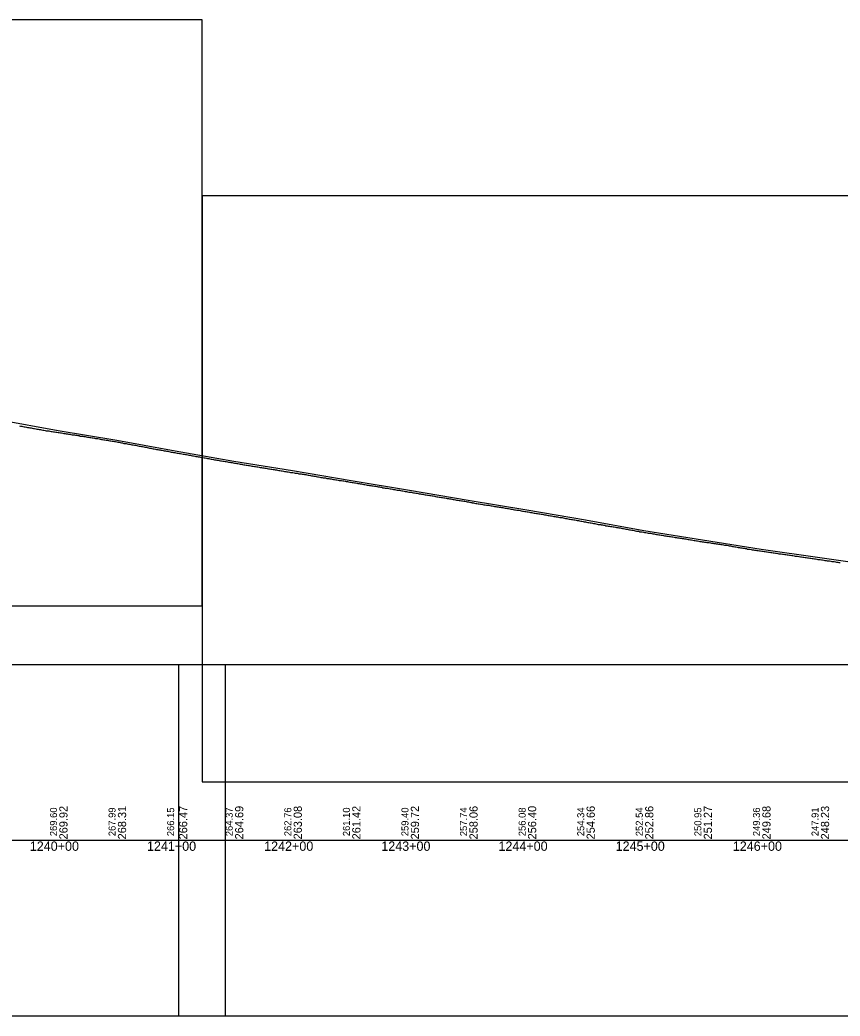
# Model space of a CAD drawing. Extents: x 2898 to 49495, y -15038 to -13538.
# Drawn here: x 13321 to 14021, y -15038 to -14188 of the extents above; entities that cross this region are included whole.
import ezdxf

# ---------------------------------------------------------------- set-up
doc = ezdxf.new("R2010")
doc.units = 0
for name, color, linetype in [('RD_DDB_Profile_EX', 7, 'Continuous'), ('RD_DDB_Profile_PR', 7, 'Continuous'), ('RD_DDB_StaTX', 7, 'Continuous'), ('RD_DDB_StripGrade', 7, 'Continuous'), ('RD_GPK_Profile_Cell', 7, 'Continuous'), ('RD_SHT_ShtClip', 7, 'Continuous')]:
    doc.layers.add(name, color=color, linetype=linetype)

msp = doc.modelspace()

# ---------------------------------------------------------------- linework, layer by layer
at = {"layer": 'RD_DDB_Profile_EX'}
for points in [[(13320.31, -14534.82), (13321.31, -14535), (13322.29, -14535.18), (13323.29, -14535.52), (13324.29, -14535.58), (13325.29, -14535.77), (13326.29, -14535.88), (13327.29, -14536.17), (13328.29, -14536.27), (13329.29, -14536.51), (13330.29, -14536.63), (13331.29, -14536.87), (13332.29, -14536.98), (13333.29, -14537.18), (13334.28, -14537.38), (13335.28, -14537.53), (13336.28, -14537.73), (13337.28, -14537.97), (13338.28, -14538.08), (13339.28, -14538.18), (13340.28, -14538.52), (13341.28, -14538.62), (13342.28, -14538.72), (13343.28, -14539.01), (13344.28, -14539.02), (13345.28, -14539.18), (13346.28, -14539.43), (13347.28, -14539.56), (13348.28, -14539.66)], [(13348.28, -14539.66), (13349.3, -14539.88), (13350.3, -14540.01), (13351.3, -14540.17), (13352.3, -14540.31), (13353.3, -14540.46), (13354.3, -14540.57), (13355.3, -14540.71), (13356.3, -14540.91), (13357.3, -14541.07), (13358.29, -14541.3), (13359.3, -14541.32), (13360.3, -14541.51), (13361.3, -14541.7), (13362.3, -14541.86), (13363.3, -14542.01), (13364.3, -14542.11), (13365.3, -14542.41), (13366.29, -14542.46), (13367.29, -14542.56), (13368.29, -14542.81), (13369.29, -14542.91), (13370.29, -14543.01), (13371.29, -14543.16), (13372.29, -14543.59), (13373.29, -14543.56), (13374.3, -14543.75), (13375.29, -14543.9), (13376.29, -14544.01), (13377.28, -14544.15), (13378.29, -14544.35), (13379.29, -14544.54), (13380.29, -14544.7), (13381.29, -14544.89), (13382.29, -14545.05), (13383.29, -14545.2), (13384.29, -14545.45), (13385.29, -14545.55), (13386.28, -14545.65), (13387.28, -14545.75), (13388.28, -14546), (13389.28, -14546.15), (13390.29, -14546.36), (13391.28, -14546.51), (13392.28, -14546.66), (13393.29, -14546.85), (13394.28, -14547), (13395.42, -14547.19), (13396.41, -14547.34), (13397.42, -14547.5), (13398.41, -14547.61), (13399.42, -14547.81), (13400.41, -14548.01), (13401.41, -14548.21), (13402.41, -14548.31), (13403.4, -14548.52), (13404.4, -14548.71), (13405.4, -14548.87), (13406.4, -14549.07), (13407.4, -14549.26), (13408.39, -14549.41), (13409.39, -14549.79), (13410.39, -14549.86), (13411.39, -14549.92), (13412.39, -14550.21), (13413.39, -14550.37), (13414.39, -14550.52), (13415.39, -14550.78), (13416.39, -14550.92), (13417.38, -14551.07), (13418.39, -14551.27), (13419.38, -14551.43), (13420.39, -14551.62), (13421.38, -14551.82), (13422.39, -14552.08), (13423.38, -14552.23), (13424.38, -14552.38), (13425.38, -14552.53), (13426.38, -14552.73), (13427.38, -14552.98), (13428.38, -14553.14), (13429.38, -14553.38), (13430.38, -14553.53), (13431.38, -14553.82), (13432.38, -14553.97), (13433.38, -14554.09), (13434.37, -14554.33), (13435.38, -14554.57), (13436.37, -14554.73), (13437.38, -14554.97), (13438.37, -14555.07), (13439.38, -14555.23), (13440.37, -14555.39), (13440.94, -14555.49), (13441.95, -14555.69), (13442.94, -14555.85), (13443.95, -14556.05), (13444.95, -14556.25), (13445.94, -14556.4), (13446.94, -14556.56), (13447.94, -14556.85)], [(13447.94, -14556.85), (13448.94, -14556.96), (13449.94, -14557.21), (13450.94, -14557.36), (13451.94, -14557.47), (13452.93, -14557.62), (13453.94, -14557.87), (13454.94, -14558.01), (13455.94, -14558.22), (13456.93, -14558.41), (13457.93, -14558.53), (13458.93, -14558.68), (13459.94, -14558.96), (13460.93, -14559.13), (13461.93, -14559.23), (13462.93, -14559.38), (13463.93, -14559.58), (13464.93, -14559.83), (13465.93, -14559.98), (13466.93, -14560.08), (13467.93, -14560.29), (13468.92, -14560.48), (13469.93, -14560.68), (13470.92, -14560.93), (13471.93, -14561.08), (13472.93, -14561.23), (13473.92, -14561.38), (13474.92, -14561.53), (13475.92, -14561.78), (13476.92, -14561.93), (13477.92, -14562.08), (13478.92, -14562.23), (13479.92, -14562.39), (13480.91, -14562.59), (13481.92, -14562.74), (13482.92, -14562.89), (13483.92, -14563.15), (13484.92, -14563.34), (13485.92, -14563.53), (13486.84, -14563.73), (13487.85, -14563.84), (13488.84, -14563.99), (13489.84, -14564.1), (13490.84, -14564.34), (13491.84, -14564.55), (13492.84, -14564.7), (13493.84, -14564.85), (13494.84, -14565), (13495.84, -14565.19), (13496.84, -14565.3), (13497.83, -14565.6), (13498.84, -14565.8), (13499.83, -14565.9), (13500.83, -14566.01), (13501.83, -14566.15), (13502.82, -14566.4), (13503.83, -14566.75), (13504.83, -14566.8), (13505.82, -14566.9), (13506.83, -14567.01), (13507.82, -14567.21), (13508.82, -14567.45), (13509.82, -14567.56), (13510.82, -14567.76), (13511.82, -14568), (13512.82, -14568.11), (13513.81, -14568.31), (13514.82, -14568.41), (13515.82, -14568.65), (13516.81, -14568.8), (13517.81, -14568.91), (13518.81, -14569.21), (13519.81, -14569.26), (13520.81, -14569.41), (13521.8, -14569.51), (13522.81, -14569.76), (13523.8, -14569.92), (13524.8, -14570.16), (13525.81, -14570.27), (13526.8, -14570.47), (13527.8, -14570.62), (13528.8, -14570.77), (13529.8, -14570.97), (13530.8, -14571.07), (13531.8, -14571.17), (13532.79, -14571.42), (13533.8, -14571.52), (13534.79, -14571.67), (13535.79, -14571.82), (13536.79, -14572.02), (13537.69, -14572.13), (13538.69, -14572.28), (13539.69, -14572.48), (13540.69, -14572.58), (13541.69, -14572.82), (13542.69, -14572.93), (13543.69, -14573.08), (13544.69, -14573.33), (13545.68, -14573.43), (13546.68, -14573.68), (13547.69, -14573.73)], [(13547.69, -14573.73), (13548.68, -14573.98), (13549.69, -14573.98), (13550.68, -14574.33), (13551.68, -14574.53), (13552.67, -14574.63), (13553.68, -14574.68), (13554.68, -14574.98), (13555.68, -14575.08), (13556.68, -14575.23), (13557.67, -14575.33), (13558.68, -14575.67), (13559.67, -14575.73), (13560.67, -14575.83), (13561.68, -14576.03), (13562.67, -14576.18), (13563.67, -14576.33), (13564.66, -14576.48), (13565.66, -14576.68), (13566.66, -14576.83), (13567.66, -14576.93), (13568.66, -14577.23), (13569.65, -14577.38), (13570.66, -14577.48), (13571.65, -14577.67), (13572.66, -14577.83), (13573.65, -14577.98), (13574.65, -14578.42), (13575.66, -14578.38), (13576.65, -14578.57), (13577.66, -14578.77), (13578.65, -14578.82), (13579.65, -14579.08), (13580.65, -14579.13), (13581.65, -14579.27), (13582.65, -14579.62), (13583.26, -14579.63), (13584.26, -14579.78), (13585.26, -14580.12), (13586.26, -14580.17), (13587.26, -14580.32), (13588.25, -14580.58), (13589.25, -14580.63), (13590.26, -14580.87), (13591.26, -14580.93), (13592.25, -14581.08), (13593.25, -14581.33), (13594.25, -14581.53), (13595.25, -14581.58), (13596.25, -14581.68), (13597.25, -14581.78), (13598.25, -14582.08), (13599.25, -14582.28), (13600.25, -14582.38), (13601.25, -14582.58), (13602.24, -14582.78), (13603.25, -14582.93), (13604.24, -14583.08), (13605.25, -14583.23), (13606.24, -14583.38), (13607.24, -14583.58), (13608.24, -14583.83), (13609.24, -14583.98), (13610.24, -14584.13), (13611.23, -14584.28), (13612.24, -14584.43), (13613.24, -14584.53), (13614.24, -14584.83), (13615.24, -14584.93), (13616.23, -14585.08), (13617.23, -14585.33), (13618.23, -14585.43), (13619.24, -14585.63), (13620.24, -14585.68), (13621.23, -14585.88), (13622.23, -14586.08), (13623.23, -14586.28), (13624.23, -14586.39), (13625.22, -14586.53), (13625.6, -14586.58), (13626.6, -14586.84), (13627.6, -14586.93), (13628.6, -14587.18), (13629.6, -14587.23), (13630.6, -14587.63), (13631.6, -14587.63), (13632.6, -14587.88), (13633.59, -14587.93), (13634.59, -14588.13), (13635.59, -14588.23), (13636.6, -14588.48), (13637.59, -14588.68), (13638.59, -14588.83), (13639.6, -14589.08), (13640.6, -14589.18), (13641.59, -14589.43), (13642.6, -14589.58), (13643.59, -14589.74), (13644.59, -14589.84), (13645.59, -14590.04), (13646.59, -14590.24)], [(13646.59, -14590.24), (13647.59, -14590.34), (13648.59, -14590.68), (13649.59, -14590.74), (13650.59, -14590.94), (13651.59, -14591.04), (13652.58, -14591.28), (13653.58, -14591.48), (13654.58, -14591.54), (13655.59, -14591.74), (13656.58, -14591.89), (13657.58, -14591.99), (13658.59, -14592.19), (13659.59, -14592.34), (13660.58, -14592.59), (13661.59, -14592.74), (13662.58, -14592.84), (13663.58, -14593.04), (13664.58, -14593.19), (13665.58, -14593.39), (13666.58, -14593.59), (13667.58, -14593.64), (13668.58, -14593.84), (13669.58, -14593.99), (13670.51, -14594.19), (13671.5, -14594.34), (13672.5, -14594.54), (13673.5, -14594.69), (13674.49, -14594.89), (13675.5, -14595.04), (13676.5, -14595.29), (13677.49, -14595.34), (13678.5, -14595.59), (13679.5, -14595.69), (13680.49, -14595.84), (13681.49, -14596.03), (13682.5, -14596.14), (13683.49, -14596.29), (13684.49, -14596.49), (13685.5, -14596.69), (13686.49, -14596.88), (13687.49, -14596.99), (13688.49, -14597.14), (13689.5, -14597.39), (13690.49, -14597.54), (13691.49, -14597.64), (13692.5, -14597.93), (13693.49, -14598.13), (13694.49, -14598.29), (13695.49, -14598.54), (13696.48, -14598.64), (13697.49, -14598.74), (13698.49, -14598.89), (13699.49, -14599.13), (13700.49, -14599.24), (13701.49, -14599.44), (13702.49, -14599.68), (13703.49, -14599.79), (13704.49, -14599.99), (13705.48, -14600.14), (13706.48, -14600.29), (13706.83, -14600.48), (13707.84, -14600.58), (13708.83, -14600.79), (13709.83, -14600.99), (13710.83, -14601.08), (13711.83, -14601.24), (13712.83, -14601.38), (13713.83, -14601.58), (13714.82, -14601.69), (13715.82, -14601.93), (13716.82, -14602.13), (13717.82, -14602.23), (13718.82, -14602.43), (13719.82, -14602.53), (13720.82, -14602.63), (13721.82, -14602.83), (13722.82, -14602.98), (13723.81, -14603.13), (13724.82, -14603.43), (13725.81, -14603.58), (13726.81, -14603.73), (13727.81, -14603.88), (13728.81, -14604.03), (13729.81, -14604.08), (13730.81, -14604.28), (13731.81, -14604.48), (13732.8, -14604.58), (13733.8, -14604.88), (13734.8, -14604.98), (13735.81, -14605.13), (13736.8, -14605.28), (13737.81, -14605.43), (13738.8, -14605.68), (13739.8, -14605.88), (13740.8, -14605.98), (13741.8, -14606.13), (13742.79, -14606.37), (13743.8, -14606.48), (13744.79, -14606.67), (13745.78, -14606.82)], [(13745.78, -14606.82), (13746.55, -14606.87), (13747.56, -14607.02), (13748.55, -14607.22), (13749.56, -14607.52), (13750.55, -14607.67), (13751.55, -14607.92), (13752.56, -14607.97), (13753.56, -14608.07), (13754.55, -14608.27), (13755.55, -14608.42), (13756.55, -14608.67), (13757.55, -14608.82), (13758.55, -14608.97), (13759.55, -14609.27), (13760.55, -14609.37), (13761.55, -14609.52), (13762.54, -14609.67), (13763.55, -14609.87), (13764.55, -14610.02), (13765.54, -14610.22), (13766.55, -14610.32), (13767.55, -14610.47), (13768.55, -14610.72), (13769.54, -14610.82), (13770.54, -14610.97), (13771.54, -14611.22), (13772.55, -14611.37), (13773.54, -14611.52), (13774.54, -14611.67), (13775.54, -14611.87), (13776.53, -14612.07), (13777.54, -14612.12), (13778.54, -14612.37), (13779.54, -14612.52), (13780.54, -14612.72), (13781.54, -14612.92), (13782.54, -14613.07), (13783.54, -14613.17), (13784.41, -14613.42), (13785.42, -14613.52), (13786.41, -14613.77), (13787.41, -14613.92), (13788.41, -14614.22), (13789.41, -14614.32), (13790.41, -14614.52), (13791.41, -14614.62), (13792.4, -14614.82), (13793.41, -14614.92), (13794.41, -14615.17), (13795.4, -14615.32), (13796.41, -14615.62), (13797.41, -14615.72), (13798.4, -14615.92), (13799.41, -14616.07), (13800.41, -14616.27), (13801.41, -14616.42), (13802.4, -14616.62), (13803.41, -14616.77), (13804.41, -14617.07), (13805.4, -14617.17), (13806.4, -14617.37), (13807.4, -14617.62), (13808.4, -14617.72), (13809.4, -14617.87), (13810.4, -14618.12), (13811.4, -14618.27), (13812.4, -14618.57), (13813.4, -14618.67), (13814.39, -14618.87), (13815.4, -14618.97), (13816.4, -14619.12), (13816.95, -14619.22), (13817.94, -14619.42), (13818.94, -14619.57), (13819.94, -14619.72), (13820.94, -14620.02), (13821.94, -14620.12), (13822.93, -14620.37), (13823.93, -14620.47), (13824.93, -14620.62), (13825.93, -14620.82), (13826.93, -14621.07), (13827.93, -14621.12), (13828.93, -14621.27), (13829.93, -14621.47), (13830.93, -14621.62), (13831.93, -14621.82), (13832.93, -14621.92), (13833.93, -14622.22), (13834.93, -14622.37), (13835.93, -14622.47), (13836.93, -14622.82), (13837.93, -14622.92), (13838.93, -14623.02), (13839.93, -14623.27), (13840.93, -14623.52), (13841.93, -14623.57), (13842.93, -14623.82), (13843.93, -14623.92), (13844.93, -14624.23)], [(13844.93, -14624.23), (13845.93, -14624.28), (13846.94, -14624.67), (13847.94, -14624.77), (13848.94, -14624.83), (13849.93, -14625.13), (13850.93, -14625.18), (13851.94, -14625.33), (13852.94, -14625.68), (13853.93, -14625.88), (13855.02, -14625.98), (13856.02, -14626.13), (13857.02, -14626.28), (13858.02, -14626.43), (13859.02, -14626.53), (13860.02, -14626.68), (13861.02, -14626.88), (13862.02, -14627.03), (13863.02, -14627.19), (13864.02, -14627.43), (13865.02, -14627.53), (13866.02, -14627.73), (13867.02, -14627.93), (13868.02, -14628.13), (13869.02, -14628.23), (13870.01, -14628.33), (13871.01, -14628.58), (13872.01, -14628.68), (13873.01, -14628.84), (13874.01, -14628.99), (13875.01, -14629.14), (13876.01, -14629.29), (13877.01, -14629.49), (13878.01, -14629.63), (13879.01, -14629.74), (13880.01, -14630.08), (13881.01, -14630.13), (13882.01, -14630.33), (13883.01, -14630.39), (13884.01, -14630.54), (13885.01, -14630.69), (13886.01, -14630.94), (13887.01, -14631.04), (13888.01, -14631.24), (13889.01, -14631.34), (13890.01, -14631.54), (13891.01, -14631.79), (13892.01, -14631.84), (13893.01, -14631.99), (13894.01, -14632.14), (13895.1, -14632.39), (13896.09, -14632.54), (13897.1, -14632.69), (13898.1, -14632.89), (13899.1, -14633.05), (13900.1, -14633.24), (13901.1, -14633.39), (13902.1, -14633.55), (13903.1, -14633.69), (13904.09, -14633.84), (13905.1, -14633.99), (13906.09, -14634.15), (13907.1, -14634.25), (13908.1, -14634.36), (13909.09, -14634.5), (13910.1, -14634.75), (13911.1, -14634.85), (13912.1, -14634.91), (13913.1, -14635.1), (13914.1, -14635.26), (13915.1, -14635.46), (13916.09, -14635.65), (13917.1, -14635.71), (13918.1, -14635.81), (13919.1, -14635.97), (13920.1, -14636.11), (13921.1, -14636.36), (13922.1, -14636.65), (13923.1, -14636.66), (13924.1, -14636.77), (13925.08, -14636.96), (13926.07, -14637.11), (13927.08, -14637.27), (13928.07, -14637.51), (13928.83, -14637.66), (13929.82, -14637.85), (13930.83, -14637.96), (13931.83, -14638.2), (13932.82, -14638.28), (13933.82, -14638.51), (13934.83, -14638.65), (13935.82, -14638.91), (13936.82, -14639.02), (13937.82, -14639.16), (13938.82, -14639.27), (13939.83, -14639.46), (13940.82, -14639.61), (13941.82, -14639.95), (13942.82, -14640), (13943.83, -14640.15), (13944.83, -14640.36)], [(13944.83, -14640.36), (13945.82, -14640.51), (13946.82, -14640.7), (13947.82, -14640.8), (13948.83, -14641), (13949.82, -14641.15), (13950.82, -14641.27), (13951.82, -14641.36), (13952.82, -14641.6), (13953.82, -14641.71), (13954.82, -14641.86), (13955.82, -14641.91), (13956.81, -14642.11), (13957.82, -14642.26), (13958.53, -14642.36), (13959.53, -14642.6), (13960.53, -14642.7), (13961.53, -14642.8), (13962.53, -14642.95), (13963.53, -14643.15), (13964.53, -14643.3), (13965.53, -14643.36), (13966.53, -14643.55), (13967.53, -14643.7), (13968.53, -14643.9), (13969.53, -14644.04), (13970.53, -14644.12), (13971.53, -14644.31), (13972.53, -14644.37), (13973.53, -14644.51), (13974.53, -14644.66), (13975.53, -14644.81), (13976.45, -14644.99), (13977.53, -14645.2), (13978.53, -14645.23), (13979.53, -14645.33), (13980.52, -14645.57), (13981.53, -14645.71), (13982.53, -14645.99), (13983.53, -14646.05), (13984.52, -14646.16), (13985.45, -14646.35), (13985.85, -14646.36), (13986.86, -14646.54), (13987.86, -14646.66), (13988.86, -14646.8), (13989.86, -14646.92), (13990.85, -14647.15), (13991.85, -14647.3), (13992.86, -14647.36), (13993.86, -14647.51), (13994.86, -14647.71), (13995.86, -14647.81), (13996.85, -14648), (13997.85, -14648.15), (13998.85, -14648.35), (13999.86, -14648.36), (14000.85, -14648.6), (14001.86, -14648.74), (14002.85, -14648.81), (14003.85, -14649), (14004.85, -14649.15), (14005.8, -14649.29), (14006.8, -14649.58), (14007.8, -14649.59), (14008.8, -14649.77), (14009.8, -14649.96), (14010.89, -14649.96), (14011.8, -14650.1), (14012.89, -14650.36), (14013.8, -14650.49), (14014.88, -14650.62), (14015.8, -14650.71), (14016.89, -14650.91), (14017.8, -14651.1), (14018.79, -14651.2), (14019.8, -14651.45), (14020.88, -14651.57)]]:
    msp.add_lwpolyline(points, dxfattribs=at)
at = {"layer": 'RD_DDB_Profile_PR'}
msp.add_lwpolyline([(13303.38, -14529.66), (13353.38, -14538.87), (13403.38, -14546.91), (13453.38, -14556.13), (13503.38, -14564.99), (13553.38, -14573.07), (13603.38, -14581.35), (13653.38, -14589.84), (13703.38, -14598.17), (13753.38, -14606.46), (13803.38, -14615.16), (13853.38, -14624.17), (13903.38, -14632.14), (13953.38, -14640.06), (14003.38, -14647.31), (14053.38, -14654.3)], dxfattribs=at)
at = {"layer": 'RD_GPK_Profile_Cell'}
msp.add_line((2976.05, -14888.47), (48721.13, -14888.47), dxfattribs=at)
at = {"layer": 'RD_SHT_ShtClip'}
for points in [[(13476.22, -14688.47), (13476.22, -14188.47), (13476.22, -14188.47), (11976.38, -14188.47), (11976.38, -14688.47)], [(14976.22, -14838.47), (14976.22, -14338.47), (14976.22, -14338.47), (13476.38, -14338.47), (13476.38, -14838.47)], [(11956.38, -14738.47), (13496.05, -14738.47), (13496.05, -15038.47), (11956.38, -15038.47)], [(13456.38, -14738.47), (14996.05, -14738.47), (14996.05, -15038.47), (13456.38, -15038.47)]]:
    msp.add_lwpolyline(points, close=True, dxfattribs=at)

# ---------------------------------------------------------------- texts
at = {"layer": 'RD_DDB_StaTX'}
for s, p in [('1240+00', (13329.18, -14897.47)), ('1241+00', (13429.18, -14897.47)), ('1242+00', (13529.18, -14897.47)), ('1243+00', (13629.18, -14897.47)), ('1244+00', (13729.18, -14897.47)), ('1245+00', (13829.18, -14897.47)), ('1246+00', (13929.18, -14897.47))]:
    msp.add_text(s, height=8, dxfattribs=at).set_placement(p)
at = {"layer": 'RD_DDB_StripGrade'}
for s, height, p in [('269.60', 6, (13352.38, -14884.98)), ('269.92', 7, (13361.38, -14887.72)), ('267.99', 6, (13402.38, -14884.98)), ('268.31', 7, (13411.38, -14887.72)), ('266.15', 6, (13452.38, -14884.98)), ('266.47', 7, (13463.52, -14887.72)), ('264.37', 6, (13502.38, -14884.98)), ('264.69', 7, (13511.38, -14887.72)), ('262.76', 6, (13552.38, -14884.98)), ('263.08', 7, (13561.38, -14887.72)), ('261.10', 6, (13602.38, -14884.98)), ('261.42', 7, (13611.38, -14887.72)), ('259.40', 6, (13652.38, -14884.98)), ('259.72', 7, (13661.38, -14887.72)), ('257.74', 6, (13702.38, -14884.98)), ('258.06', 7, (13711.38, -14887.72)), ('256.08', 6, (13752.38, -14884.98)), ('256.40', 7, (13761.38, -14887.72)), ('254.34', 6, (13802.38, -14884.98)), ('254.66', 7, (13811.38, -14887.72)), ('252.54', 6, (13852.38, -14884.98)), ('252.86', 7, (13861.38, -14887.72)), ('250.95', 6, (13902.38, -14884.98)), ('251.27', 7, (13911.38, -14887.72)), ('249.36', 6, (13952.38, -14884.98)), ('249.68', 7, (13961.38, -14887.72)), ('247.91', 6, (14002.38, -14884.98)), ('248.23', 7, (14011.38, -14887.72))]:
    msp.add_text(s, height=height, rotation=90, dxfattribs=at).set_placement(p)

doc.saveas('drawing.dxf')
